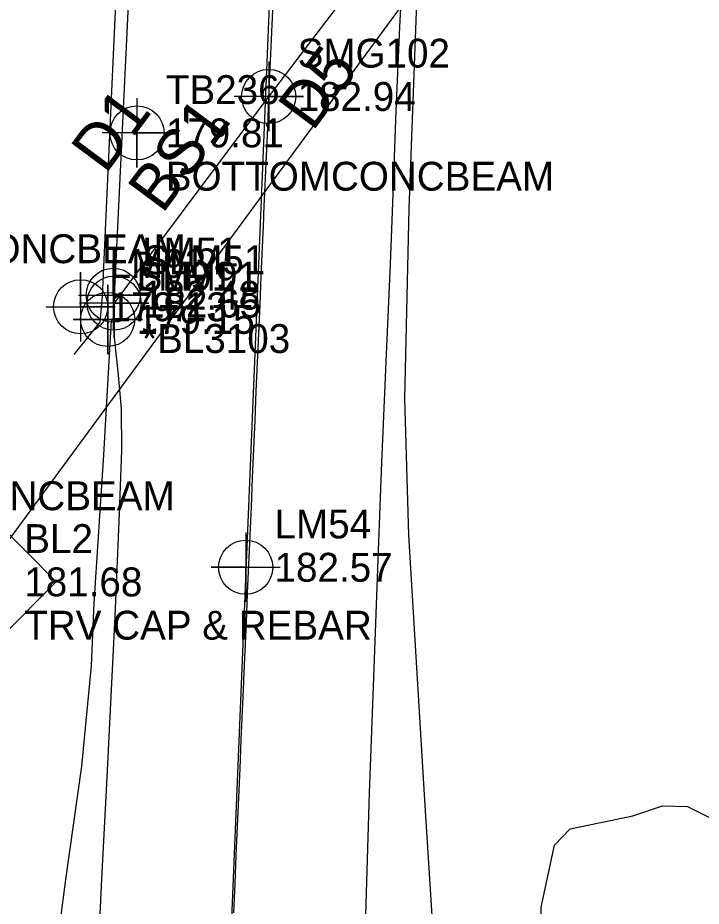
# Model space of a CAD drawing. Extents: x 2262665 to 2270527, y 505476 to 514960.
# Drawn here: x 2266305.4 to 2266364.6, y 510424.3 to 510501.2 of the extents above; entities that cross this region are included whole.
import ezdxf

# ---------------------------------------------------------------- set-up
doc = ezdxf.new("R2010")
doc.units = 0
for name, color, linetype in [('CTL Secondary Horizontal and Vertical CELL', 7, 'Continuous'), ('CTL Secondary Horizontal and Vertical Cogo Comment', 7, 'Continuous'), ('CTL Secondary Horizontal and Vertical Cogo Elevation', 7, 'Continuous'), ('CTL Secondary Horizontal and Vertical Cogo Number', 7, 'Continuous'), ('Default Symbol CELL', 7, 'Continuous'), ('Default Symbol Cogo Comment', 7, 'Continuous'), ('Default Symbol Cogo Elevation', 7, 'Continuous'), ('Default Symbol Cogo Number', 7, 'Continuous'), ('Exist Guardrail', 7, 'Continuous'), ('Exist Guardrail Text', 7, 'Continuous'), ('Exist Horizontal Alignment', 7, 'Continuous'), ('Exist Right of Way Line', 7, 'Continuous'), ('Exist Roads EOP', 7, 'Continuous'), ('Exist Roads EOT', 7, 'Continuous'), ('Exist Roads EOT Cogo Elevation', 7, 'Continuous'), ('Exist Roads EOT Cogo Number', 7, 'Continuous'), ('Exist Roads EOT Cogo Point CELL', 7, 'Continuous'), ('Exist Structure Major Bridge Seam Cogo Comment', 7, 'Continuous'), ('Exist Structure Major Bridge Seam Cogo Elevation', 7, 'Continuous'), ('Exist Structure Major Bridge Seam Cogo Number', 7, 'Continuous'), ('Exist Structure Major Bridge Seam Cogo Point CELL', 7, 'Continuous'), ('Exist Structure Major Deck Tunnel Box Culvert', 7, 'Continuous'), ('Exist Structure Major Deck Tunnel Box Culvert Cogo Elevation', 7, 'Continuous'), ('Exist Structure Major Deck Tunnel Box Culvert Cogo Number', 7, 'Continuous'), ('Exist Structure Major Deck Tunnel Box Culvert Cogo Point CELL', 7, 'Continuous'), ('Exist Structure Major Deck Tunnel Box Culvert Text', 7, 'Continuous'), ('Exist Vegetation Hedge Row', 7, 'Continuous')]:
    doc.layers.add(name, color=color, linetype=linetype)

msp = doc.modelspace()

# ---------------------------------------------------------------- linework, layer by layer
at = {"layer": 'CTL Secondary Horizontal and Vertical CELL'}
msp.add_lwpolyline([(2266298.241, 510452.365), (2266303.483, 510457.607), (2266308.733, 510452.357), (2266303.491, 510447.115)], close=True, dxfattribs=at)
at = {"layer": 'Default Symbol CELL'}
for points in [[(2266327.123, 510497.387), (2266327.123, 510491.387), (2266327.123, 510494.387), (2266330.123, 510494.387), (2266324.123, 510494.387)], [(2266315.715, 510494.232), (2266315.715, 510488.232), (2266315.715, 510491.232), (2266318.715, 510491.232), (2266312.715, 510491.232)], [(2266313.738, 510479.49), (2266313.738, 510473.49), (2266313.738, 510476.49), (2266316.738, 510476.49), (2266310.738, 510476.49)], [(2266313.182, 510478.079), (2266313.182, 510472.079), (2266313.182, 510475.079), (2266316.182, 510475.079), (2266310.182, 510475.079)]]:
    msp.add_lwpolyline(points, dxfattribs=at)
for centre in [(2266327.123, 510494.387), (2266315.715, 510491.232), (2266313.738, 510476.49), (2266313.182, 510475.079)]:
    msp.add_circle(centre, 2.344, dxfattribs=at)
at = {"layer": 'Exist Guardrail'}
for points in [[(2266310.275, 510472.029), (2266312.516, 510474.848), (2266312.727, 510477.084), (2266316.621, 510562.638), (2266320.054, 510647.377), (2266321.754, 510688.765), (2266321.754, 510688.765), (2266321.886, 510690.484), (2266321.011, 510691.957), (2266320.201, 510692.519)], [(2266340.224, 510511.066), (2266339.256, 510484.643), (2266338.881, 510468.223), (2266339.228, 510456.395), (2266340.615, 510433.451), (2266341.524, 510418.909), (2266341.983, 510406.294), (2266341.94, 510393.06), (2266341.157, 510377.418), (2266339.545, 510343.252), (2266338.129, 510314.393), (2266336.908, 510286.44), (2266335.263, 510254.311), (2266334.387, 510233.278)], [(2266300.519, 510372.209), (2266303.258, 510387.411), (2266305.642, 510401.575), (2266308.099, 510415.325), (2266309.548, 510426.579), (2266310.938, 510436.398), (2266311.78, 510445.083), (2266312.023, 510450.497), (2266312.845, 510463.363), (2266313.518, 510475.022)]]:
    msp.add_lwpolyline(points, dxfattribs=at)
at = {"layer": 'Exist Guardrail Text'}
msp.add_line((2266327.115, 510494.211), (2266327.13, 510494.562), dxfattribs=at)
at = {"layer": 'Exist Horizontal Alignment'}
msp.add_line((2266320.496, 510340.107), (2266385.321, 511909.143), dxfattribs=at)
at = {"layer": 'Exist Right of Way Line'}
msp.add_line((2266927.916, 511303.767), (2265541.794, 509418.488), dxfattribs=at)
at = {"layer": 'Exist Roads EOP'}
for points in [[(2266338.758, 510506.552), (2266338.444, 510500.42), (2266338.122, 510493.156), (2266337.889, 510486.706), (2266337.641, 510479.862), (2266337.272, 510471.415), (2266336.889, 510462.702), (2266336.6, 510455.063), (2266336.349, 510447.991), (2266336.08, 510440.981), (2266335.829, 510434.087), (2266335.631, 510427.363), (2266335.427, 510420.509), (2266335.155, 510413.226), (2266334.866, 510405.762), (2266334.609, 510398.364), (2266334.385, 510391.341), (2266334.192, 510385.003), (2266333.969, 510378.479), (2266333.656, 510370.896), (2266333.303, 510362.906), (2266332.962, 510355.163)], [(2266309.283, 510353.995), (2266309.688, 510362.791), (2266310.101, 510371.882), (2266310.522, 510381.286), (2266310.953, 510390.505), (2266311.393, 510399.517), (2266311.829, 510408.685), (2266312.258, 510417.953), (2266312.686, 510426.626), (2266313.12, 510434.846), (2266313.581, 510444.174), (2266313.823, 510449.351), (2266314.216, 510458.301), (2266314.411, 510463.761), (2266314.377, 510467.324), (2266314.084, 510470.583), (2266313.782, 510473.487), (2266313.722, 510475.986)]]:
    msp.add_lwpolyline(points, dxfattribs=at)
at = {"layer": 'Exist Roads EOT'}
for points in [[(2266327.5, 510503.076), (2266327.391, 510500.579), (2266327.283, 510498.081), (2266327.175, 510495.584), (2266327.13, 510494.562)], [(2266327.115, 510494.211), (2266327.007, 510491.714), (2266326.898, 510489.216), (2266326.79, 510486.719), (2266326.682, 510484.221), (2266326.665, 510483.838), (2266326.558, 510481.34), (2266326.45, 510478.842), (2266326.343, 510476.345), (2266326.235, 510473.847), (2266326.128, 510471.349), (2266326.021, 510468.852), (2266325.913, 510466.354), (2266325.806, 510463.857), (2266325.699, 510461.359), (2266325.591, 510458.861), (2266325.484, 510456.364), (2266325.376, 510453.866), (2266325.269, 510451.369), (2266325.162, 510448.871), (2266325.054, 510446.373), (2266324.947, 510443.876), (2266324.938, 510443.67), (2266324.829, 510441.172), (2266324.721, 510438.675), (2266324.612, 510436.177), (2266324.503, 510433.68), (2266324.395, 510431.182), (2266324.286, 510428.685), (2266324.178, 510426.187), (2266324.069, 510423.689)]]:
    msp.add_lwpolyline(points, dxfattribs=at)
at = {"layer": 'Exist Roads EOT Cogo Point CELL'}
msp.add_lwpolyline([(2266325.129, 510456.615), (2266325.129, 510450.615), (2266325.129, 510453.615), (2266322.129, 510453.615), (2266328.129, 510453.615)], dxfattribs=at)
msp.add_circle((2266325.129, 510453.615), 2.344, dxfattribs=at)
at = {"layer": 'Exist Structure Major Bridge Seam Cogo Point CELL'}
msp.add_lwpolyline([(2266310.658, 510477.173), (2266316.658, 510477.173), (2266313.658, 510477.173), (2266313.658, 510480.173), (2266313.658, 510474.173)], dxfattribs=at)
msp.add_circle((2266313.658, 510477.173), 2.344, dxfattribs=at)
at = {"layer": 'Exist Structure Major Deck Tunnel Box Culvert'}
msp.add_lwpolyline([(2266339.3, 510510.447), (2266326.148, 510493.102), (2266316.383, 510480.04), (2266313.738, 510476.49), (2266315.179, 510506.564)], dxfattribs=at)
at = {"layer": 'Exist Structure Major Deck Tunnel Box Culvert Cogo Point CELL'}
for points in [[(2266307.841, 510476.175), (2266313.841, 510476.175), (2266310.841, 510476.175), (2266310.841, 510479.175), (2266310.841, 510473.175)], [(2266310.182, 510475.079), (2266316.182, 510475.079), (2266313.182, 510475.079), (2266313.182, 510478.079), (2266313.182, 510472.079)]]:
    msp.add_lwpolyline(points, dxfattribs=at)
for centre in [(2266310.841, 510476.175), (2266313.182, 510475.079)]:
    msp.add_circle(centre, 2.344, dxfattribs=at)
at = {"layer": 'Exist Vegetation Hedge Row'}
for points in [[(2266345.244, 510259.359), (2266345.731, 510265.009), (2266346.475, 510269.451), (2266345.971, 510275.192), (2266347.937, 510288.026), (2266348.817, 510295.932), (2266349.565, 510302.814), (2266350.718, 510312.063), (2266351.103, 510323.01), (2266350.461, 510323.661), (2266348.187, 510325.461), (2266347.055, 510330.003), (2266347.142, 510336.134), (2266347.465, 510365.168), (2266348.151, 510368.987), (2266348.659, 510387.244), (2266350.434, 510399.615), (2266350.712, 510424.179), (2266351.875, 510429.544), (2266353.227, 510430.972), (2266355.601, 510431.454), (2266358.656, 510432.096), (2266361.214, 510432.968), (2266363.38, 510432.9)], [(2266363.38, 510432.9), (2266371.224, 510428.957)]]:
    msp.add_lwpolyline(points, dxfattribs=at)

# ---------------------------------------------------------------- texts
at = {"layer": 'CTL Secondary Horizontal and Vertical Cogo Comment'}
msp.add_text('TRV CAP & REBAR', height=2.5, dxfattribs=at).set_placement((2266305.956, 510447.348))
at = {"layer": 'CTL Secondary Horizontal and Vertical Cogo Elevation'}
msp.add_text('181.68', height=2.5, dxfattribs=at).set_placement((2266305.956, 510451.098))
at = {"layer": 'CTL Secondary Horizontal and Vertical Cogo Number'}
msp.add_text('BL2', height=2.5, dxfattribs=at).set_placement((2266305.956, 510454.848))
at = {"layer": 'Default Symbol Cogo Comment'}
for p in [(2266318.215, 510486.232), (2266286.322, 510479.951), (2266285.364, 510458.56)]:
    msp.add_text('BOTTOMCONCBEAM', height=2.5, dxfattribs=at).set_placement(p)
at = {"layer": 'Default Symbol Cogo Elevation'}
for s, p in [('182.94', (2266329.623, 510493.137)), ('179.81', (2266318.215, 510489.982)), ('182.65', (2266316.238, 510475.24)), ('179.15', (2266315.682, 510473.829))]:
    msp.add_text(s, height=2.5, dxfattribs=at).set_placement(p)
at = {"layer": 'Default Symbol Cogo Number'}
for s, p in [('SMG102', (2266329.623, 510496.887)), ('TB236', (2266318.215, 510493.732)), ('SLM51', (2266316.238, 510478.99)), ('SLM91', (2266315.682, 510477.579))]:
    msp.add_text(s, height=2.5, dxfattribs=at).set_placement(p)
at = {"layer": 'Exist Roads EOT Cogo Elevation'}
msp.add_text('182.57', height=2.5, dxfattribs=at).set_placement((2266327.629, 510452.365))
at = {"layer": 'Exist Roads EOT Cogo Number'}
msp.add_text('LM54', height=2.5, dxfattribs=at).set_placement((2266327.629, 510456.115))
at = {"layer": 'Exist Structure Major Bridge Seam Cogo Comment'}
msp.add_text('*BL3103', height=2.5, dxfattribs=at).set_placement((2266316.158, 510472.173))
at = {"layer": 'Exist Structure Major Bridge Seam Cogo Elevation'}
msp.add_text('182.48', height=2.5, dxfattribs=at).set_placement((2266316.158, 510475.923))
at = {"layer": 'Exist Structure Major Bridge Seam Cogo Number'}
msp.add_text('LM51', height=2.5, dxfattribs=at).set_placement((2266316.158, 510479.673))
at = {"layer": 'Exist Structure Major Deck Tunnel Box Culvert Cogo Elevation'}
for s, p in [('179.13', (2266313.341, 510474.925)), ('179.15', (2266315.682, 510473.829))]:
    msp.add_text(s, height=2.5, dxfattribs=at).set_placement(p)
at = {"layer": 'Exist Structure Major Deck Tunnel Box Culvert Cogo Number'}
for s, p in [('LM92', (2266313.341, 510478.675)), ('LM91', (2266315.682, 510477.579))]:
    msp.add_text(s, height=2.5, dxfattribs=at).set_placement(p)
at = {"layer": 'Exist Structure Major Deck Tunnel Box Culvert Text'}
for s, p in [('D5', (2266330.908, 510491.275)), ('    D1', (2266309.445, 510482.821)), ('BS1', (2266317.907, 510484.139))]:
    msp.add_text(s, height=4, rotation=53.33023, dxfattribs=at).set_placement(p)

doc.saveas('drawing.dxf')
